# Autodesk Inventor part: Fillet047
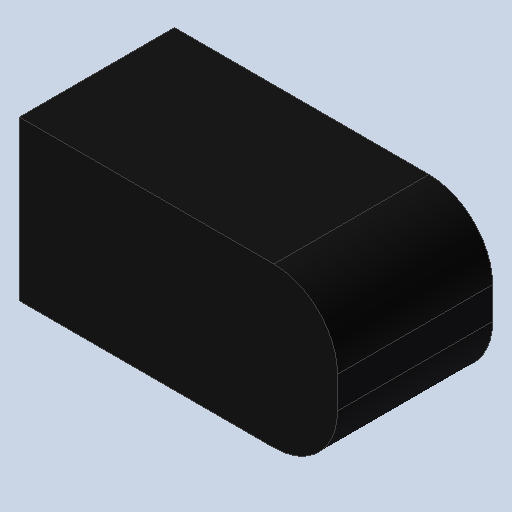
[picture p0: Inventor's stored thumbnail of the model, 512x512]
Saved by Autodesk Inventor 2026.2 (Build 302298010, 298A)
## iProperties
Created: 2026-10
Part Number: Fillet047
Material: Générique
Document SubType Name: Modeling
Designer: mel
Density: 1 g/cm^3
Appearance: Par défaut
Author: mel
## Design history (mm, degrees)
feature "Base1"
node "Solide1"
